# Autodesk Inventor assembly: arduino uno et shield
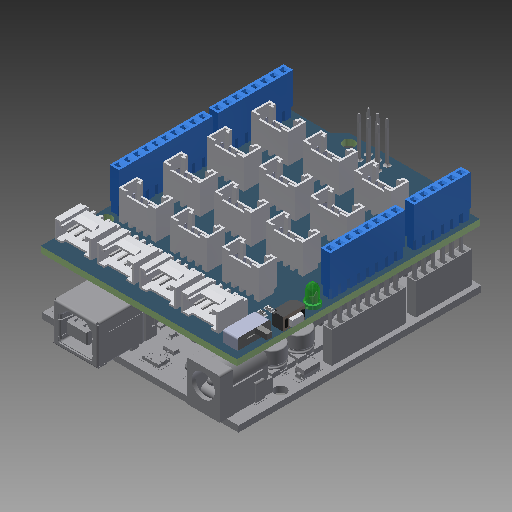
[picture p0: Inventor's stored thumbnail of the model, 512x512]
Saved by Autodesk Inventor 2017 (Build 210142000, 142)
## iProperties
Part Number: arduino uno et shield
Material: Générique
Document SubType Name: Assembly
Designer: ficho
Author: ficho
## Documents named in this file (3)
- G:\travail\année 2017-2018\1STI2D\challenge\arduino uno et shield.iam
- G:\travail\année 2017-2018\1STI2D\challenge\pièces electro step\Grove shield Uno.ipt
- G:\travail\année 2017-2018\1STI2D\challenge\pièces electro step\arduino uno.ipt
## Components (2 placed, 2 different names)
1. Grove shield Uno:1 — Placage:1
2. arduino uno:1 — Placage:1
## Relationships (1: Mate 1)
- Placage:1 [Mate]: Grove shield Uno:1 ↔ arduino uno:1
